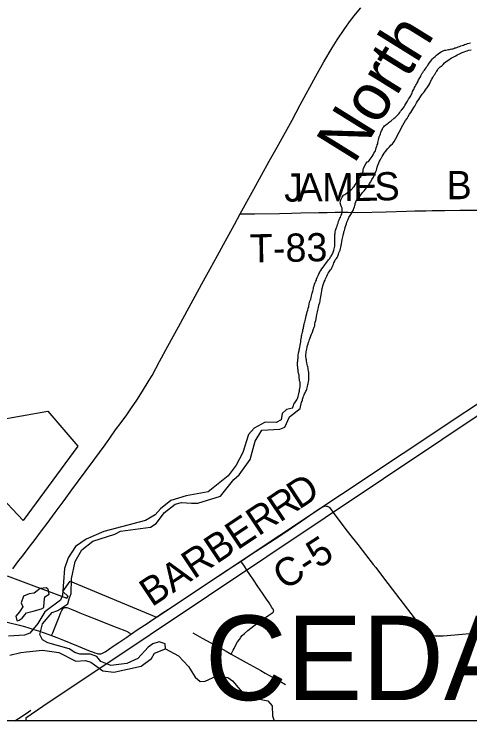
# Model space of a CAD drawing. Extents: x -19.5 to 44.1, y 0 to 22.
# Drawn here: x 4.397 to 5.315, y 17.897 to 19.322 of the extents above; entities that cross this region are included whole.
import ezdxf

# ---------------------------------------------------------------- set-up
doc = ezdxf.new("R2010")
doc.units = 0
for name, color, linetype in [('GM_X_City_Street', 7, 'Continuous'), ('GM_X_Corporation', 7, 'Continuous'), ('GM_X_County_Road', 7, 'Continuous'), ('GM_X_County_Road_Text', 7, 'Continuous'), ('GM_X_Minor_Lake', 7, 'Continuous'), ('GM_X_Minor_River', 7, 'Continuous'), ('GM_X_Minor_River_Text', 7, 'Continuous'), ('GM_X_Township_Road', 7, 'Continuous'), ('GM_X_Township_Road_Text', 7, 'Continuous'), ('GM_X_Township_Subdivision', 7, 'Continuous'), ('GM_X_Township_Text', 7, 'Continuous'), ('GM_X_US_Route', 7, 'Continuous'), ('SH_Data', 7, 'Continuous')]:
    doc.layers.add(name, color=color, linetype=linetype)

msp = doc.modelspace()

# ---------------------------------------------------------------- linework, layer by layer
at = {"layer": 'GM_X_City_Street'}
for points in [[(5.0264, 18.3303), (5.0279, 18.3302), (5.0292, 18.3297), (5.0305, 18.329), (5.0317, 18.328), (5.0344, 18.3248)], [(5.0344, 18.3248), (5.035, 18.3241), (5.0397, 18.3174)], [(4.8612, 18.2088), (4.8563, 18.2164), (4.8544, 18.2194)], [(4.8662, 18.2012), (4.8612, 18.2088)], [(4.4728, 18.0694), (4.474, 18.0721), (4.4751, 18.0745), (4.48, 18.0866), (4.4867, 18.1034), (4.4918, 18.1155), (4.4938, 18.1201), (4.4954, 18.1231), (4.496, 18.1239), (4.4967, 18.1245), (4.4979, 18.1253), (4.4994, 18.1258)], [(4.4994, 18.1258), (4.5011, 18.126), (4.5036, 18.1258), (4.5053, 18.1253), (4.5087, 18.1239), (4.516, 18.1211), (4.5237, 18.1179), (4.5298, 18.1154), (4.5433, 18.1099), (4.5638, 18.1016), (4.5988, 18.0878), (4.6063, 18.085), (4.6207, 18.0792), (4.6236, 18.078), (4.6263, 18.0766), (4.6281, 18.0757), (4.6296, 18.0745), (4.6308, 18.0731), (4.632, 18.0716)], [(4.3518, 18.1035), (4.363, 18.1009), (4.4081, 18.0901), (4.4183, 18.0872), (4.4273, 18.0848), (4.4374, 18.0817), (4.4464, 18.0786), (4.4582, 18.0746), (4.4726, 18.0694), (4.4728, 18.0694)], [(4.632, 18.0716), (4.647, 18.0819), (4.6651, 18.0939), (4.6749, 18.1005), (4.684, 18.1063)], [(4.4728, 18.0694), (4.4834, 18.0652), (4.4971, 18.0598), (4.5266, 18.048), (4.5508, 18.0381), (4.5552, 18.0365), (4.5601, 18.0347), (4.5647, 18.0331), (4.5667, 18.0327), (4.5682, 18.0324), (4.57, 18.0324)], [(4.57, 18.0324), (4.572, 18.0327), (4.574, 18.0332), (4.5756, 18.0338), (4.5769, 18.0344), (4.5807, 18.0365), (4.5874, 18.0409), (4.5991, 18.0492), (4.6084, 18.0555), (4.6245, 18.0662), (4.632, 18.0716)], [(4.3988, 17.8973), (4.4134, 17.9069), (4.4265, 17.9158), (4.431, 17.919)]]:
    msp.add_lwpolyline(points, dxfattribs=at)
at = {"layer": 'GM_X_Corporation'}
for points in [[(5.9639, 18.9356), (4.6712, 18.0706), (4.4553, 17.9261), (4.4208, 17.903), (4.4213, 17.8973), (3.9099, 17.8973), (3.9093, 17.9023), (3.9787, 17.9347), (4.0003, 17.9368), (4.0039, 17.977), (3.9735, 17.9646), (3.9645, 17.9824), (3.9246, 17.9471), (3.9155, 17.939), (3.9091, 17.934), (3.8943, 17.9218), (3.8888, 17.9158), (3.8811, 17.908), (3.8706, 17.8973), (3.5544, 17.8973), (3.5192, 17.9083)], [(4.3834, 18.1894), (4.5034, 18.1448), (4.5061, 18.148), (4.4957, 18.1583), (4.5103, 18.1788), (4.684, 18.1063), (5.9282, 18.9339)], [(4.3589, 18.5029), (4.4654, 18.5216), (4.5258, 18.451), (4.4159, 18.3009), (4.3621, 18.3579)]]:
    msp.add_lwpolyline(points, dxfattribs=at)
at = {"layer": 'GM_X_County_Road'}
for points in [[(4.8544, 18.2194), (4.8743, 18.2324), (4.9304, 18.2691), (4.9531, 18.2842), (4.9767, 18.3004), (5.01, 18.3233), (5.0141, 18.3261), (5.0193, 18.329), (5.0212, 18.3298), (5.0228, 18.3302), (5.0248, 18.3304), (5.0264, 18.3303)], [(5.0397, 18.3174), (5.0638, 18.2854), (5.0729, 18.2736), (5.0894, 18.2527), (5.1208, 18.2125), (5.1258, 18.2062), (5.1434, 18.1829), (5.1965, 18.114), (5.216, 18.0882), (5.2208, 18.0826), (5.2239, 18.0796), (5.2264, 18.0773), (5.2289, 18.0754), (5.2315, 18.0737), (5.2342, 18.0723), (5.2371, 18.0711), (5.2398, 18.0701), (5.2429, 18.0694), (5.2463, 18.0689), (5.2498, 18.0686), (5.2551, 18.0685), (5.2612, 18.0687), (5.2699, 18.0693), (5.3454, 18.076)], [(4.684, 18.1063), (4.6956, 18.1142), (4.7086, 18.1227), (4.7568, 18.1545), (4.7883, 18.1755), (4.8208, 18.1974), (4.8544, 18.2194)]]:
    msp.add_lwpolyline(points, dxfattribs=at)
at = {"layer": 'GM_X_Minor_Lake'}
for points in [[(4.436, 18.1182), (4.4524, 18.1233), (4.4574, 18.1255), (4.4576, 18.1373), (4.4596, 18.1475), (4.4677, 18.153), (4.4663, 18.1625), (4.4618, 18.1653), (4.4496, 18.164), (4.4377, 18.155), (4.4274, 18.1533), (4.416, 18.1485), (4.4116, 18.135), (4.4153, 18.1273), (4.4083, 18.1172), (4.4009, 18.1082), (4.4031, 18.0998)], [(4.4031, 18.0998), (4.4044, 18.099), (4.4076, 18.1005), (4.4137, 18.1042), (4.4193, 18.1113), (4.4224, 18.1151), (4.436, 18.1182)]]:
    msp.add_lwpolyline(points, dxfattribs=at)
at = {"layer": 'GM_X_Minor_River'}
for points in [[(5.1375, 19.0866), (5.1387, 19.0885), (5.1403, 19.0922), (5.1422, 19.0945), (5.1433, 19.0964), (5.1457, 19.0982), (5.1487, 19.1005), (5.151, 19.102), (5.1526, 19.1038), (5.1548, 19.1053), (5.1568, 19.1068), (5.1629, 19.1117), (5.1648, 19.1132), (5.1675, 19.1158), (5.1706, 19.1192), (5.1721, 19.121), (5.1741, 19.1237), (5.1756, 19.1259), (5.1775, 19.1282), (5.1814, 19.1327), (5.1829, 19.1349), (5.1841, 19.1376), (5.1884, 19.144), (5.1899, 19.1466), (5.1919, 19.15), (5.1938, 19.153), (5.1953, 19.1553), (5.1961, 19.1572), (5.1969, 19.1591), (5.1981, 19.1613), (5.1989, 19.1632), (5.2, 19.1659), (5.2016, 19.1689), (5.2028, 19.1711), (5.2035, 19.1738), (5.2051, 19.176), (5.2063, 19.1783), (5.2078, 19.1802), (5.2082, 19.1821), (5.2105, 19.1855), (5.2109, 19.1874), (5.2121, 19.1892), (5.2133, 19.1915), (5.2144, 19.1934), (5.2156, 19.1956), (5.2167, 19.1975), (5.2179, 19.1998), (5.2191, 19.2024), (5.2206, 19.2043), (5.2222, 19.2066), (5.2237, 19.2088), (5.2253, 19.2111), (5.2272, 19.2137), (5.2288, 19.2164), (5.2303, 19.2182), (5.2315, 19.2201), (5.2357, 19.2261), (5.238, 19.2291), (5.2403, 19.2318), (5.2423, 19.2333), (5.2457, 19.2366), (5.248, 19.2389), (5.2515, 19.2415), (5.2538, 19.2434), (5.2572, 19.2456), (5.2603, 19.2471), (5.2626, 19.2482), (5.2648, 19.2489), (5.2671, 19.2492), (5.2694, 19.25), (5.2725, 19.2503), (5.2744, 19.2507), (5.2763, 19.251), (5.2789, 19.2517), (5.2808, 19.2517), (5.2827, 19.2524), (5.285, 19.2535), (5.2869, 19.2539), (5.2892, 19.2546), (5.2915, 19.2557), (5.2942, 19.2565), (5.2968, 19.2576), (5.2995, 19.2583), (5.3022, 19.2594), (5.3045, 19.2605), (5.3079, 19.2612), (5.3106, 19.2623), (5.3136, 19.2634), (5.3167, 19.2641)], [(5.2387, 19.1904), (5.241, 19.1941), (5.2429, 19.1979), (5.2445, 19.2002), (5.246, 19.2024), (5.2476, 19.2051), (5.2488, 19.207), (5.2499, 19.2088), (5.2511, 19.2107), (5.2534, 19.2137), (5.2553, 19.2156), (5.2572, 19.2171), (5.2592, 19.2182), (5.2615, 19.2204), (5.2642, 19.2234), (5.2672, 19.2257), (5.2733, 19.2302), (5.2756, 19.2313), (5.2783, 19.2335), (5.2818, 19.235), (5.2841, 19.2365), (5.2867, 19.2379), (5.2898, 19.2394), (5.2928, 19.2409), (5.2959, 19.2424), (5.2997, 19.2442), (5.3035, 19.2457), (5.307, 19.2468), (5.31, 19.2479), (5.3134, 19.249), (5.3176, 19.25)], [(5.0529, 18.8435), (5.054, 18.8461), (5.0548, 18.8492), (5.0556, 18.8518), (5.0564, 18.8552), (5.0569, 18.8586), (5.0573, 18.8628), (5.0581, 18.8673), (5.0589, 18.87), (5.0593, 18.8726), (5.0601, 18.8757), (5.0609, 18.8787), (5.0613, 18.881), (5.0617, 18.8829), (5.0625, 18.8855), (5.0633, 18.8885), (5.0641, 18.892), (5.0653, 18.8954), (5.0665, 18.8991), (5.0677, 18.9025), (5.0692, 18.9067), (5.0712, 18.9116), (5.0766, 18.9199), (5.0778, 18.9222), (5.0789, 18.924), (5.0809, 18.9274), (5.0817, 18.9301), (5.0828, 18.9331), (5.0836, 18.9357), (5.084, 18.938), (5.0844, 18.9399), (5.0856, 18.9437), (5.0864, 18.9456), (5.088, 18.9478), (5.0891, 18.9497), (5.0907, 18.9527), (5.0937, 18.955), (5.0961, 18.9584), (5.0991, 18.9621), (5.1022, 18.9655), (5.1049, 18.9689), (5.1072, 18.9715), (5.1092, 18.9741), (5.1115, 18.9771), (5.1134, 18.9802), (5.1157, 18.9839), (5.1181, 18.9881), (5.1212, 18.9933), (5.1231, 18.9975), (5.1247, 19.0009), (5.1259, 19.0043), (5.127, 19.0073), (5.1278, 19.01), (5.1286, 19.0134), (5.1302, 19.0175), (5.1318, 19.0217), (5.1333, 19.0251), (5.1349, 19.0273), (5.1361, 19.0304), (5.1376, 19.0322), (5.1388, 19.0345), (5.1407, 19.0379), (5.143, 19.0417), (5.1461, 19.0458), (5.1496, 19.0503), (5.1531, 19.0541), (5.1562, 19.0574), (5.1592, 19.0604), (5.1615, 19.0631), (5.1631, 19.0653), (5.1658, 19.0698), (5.1732, 19.0838), (5.1755, 19.0883), (5.1779, 19.0932), (5.1806, 19.0977), (5.1829, 19.1023), (5.1856, 19.1072), (5.1887, 19.1113), (5.191, 19.1154), (5.1938, 19.12), (5.1965, 19.1233), (5.1984, 19.1267), (5.2003, 19.1301), (5.2023, 19.1335), (5.2042, 19.1365), (5.2058, 19.1392), (5.2077, 19.1426), (5.21, 19.1463), (5.2123, 19.1493), (5.2143, 19.1527), (5.2166, 19.1561), (5.2193, 19.1603), (5.2216, 19.1629), (5.2236, 19.1659), (5.2259, 19.1689), (5.2282, 19.1715), (5.2301, 19.1745), (5.2325, 19.1783), (5.2344, 19.1821), (5.2363, 19.1858), (5.2387, 19.1904)], [(5.0252, 18.8192), (5.0264, 18.8211), (5.0291, 18.8244), (5.0306, 18.8267), (5.0333, 18.8289), (5.0349, 18.8323), (5.036, 18.8342), (5.0372, 18.8361), (5.0399, 18.8418), (5.0411, 18.8459), (5.0419, 18.849), (5.0427, 18.8516), (5.0431, 18.8543), (5.0435, 18.8573), (5.0436, 18.8607), (5.0433, 18.8641), (5.0433, 18.8668), (5.0433, 18.8695), (5.0434, 18.8729), (5.0434, 18.8752), (5.0434, 18.8774), (5.0438, 18.8797), (5.0442, 18.8827), (5.045, 18.8854), (5.0462, 18.8896), (5.047, 18.8918), (5.0478, 18.8945), (5.0486, 18.8975), (5.0498, 18.9005), (5.051, 18.9043), (5.0521, 18.9069), (5.0525, 18.9088), (5.0533, 18.9107), (5.0545, 18.9126), (5.0553, 18.9149), (5.0564, 18.9168), (5.0572, 18.9187), (5.0584, 18.9224), (5.0584, 18.9255), (5.0581, 18.9274), (5.0578, 18.9308), (5.0566, 18.9331), (5.0556, 18.9369), (5.0541, 18.9411), (5.0545, 18.9438), (5.0553, 18.9468), (5.0561, 18.9491), (5.058, 18.9525), (5.0592, 18.9547), (5.0611, 18.9566), (5.0634, 18.9585), (5.0653, 18.9596), (5.068, 18.9614), (5.0711, 18.9641), (5.073, 18.9655), (5.0749, 18.967), (5.0768, 18.9685), (5.0788, 18.9704), (5.0803, 18.9727), (5.0822, 18.9741), (5.0842, 18.9775), (5.0861, 18.9802), (5.0876, 18.9824), (5.0892, 18.9858), (5.0919, 18.9888), (5.0938, 18.9915), (5.095, 18.9933), (5.0961, 18.9952), (5.0969, 18.9975), (5.0985, 19.0001), (5.0997, 19.0032), (5.1001, 19.005), (5.1005, 19.0077), (5.1013, 19.0104), (5.1021, 19.0138), (5.1056, 19.0202), (5.1087, 19.0239), (5.1109, 19.025), (5.1133, 19.0277), (5.1144, 19.0295), (5.1163, 19.0322), (5.1187, 19.0348), (5.1206, 19.0378), (5.1222, 19.0416), (5.1241, 19.0442), (5.1249, 19.0461), (5.1261, 19.0491), (5.1269, 19.0525), (5.128, 19.0556), (5.1288, 19.0582), (5.1296, 19.0605), (5.13, 19.0628), (5.1308, 19.0654), (5.1316, 19.0684), (5.132, 19.0711), (5.1328, 19.0741), (5.134, 19.0768), (5.1348, 19.0786), (5.1352, 19.0805), (5.1363, 19.0828), (5.1375, 19.0866)], [(4.9735, 18.5272), (4.9762, 18.5399), (4.9773, 18.5417), (4.9781, 18.5436), (4.9785, 18.5455), (4.9797, 18.5489), (4.9805, 18.5519), (4.9817, 18.5546), (4.9825, 18.5565), (4.9836, 18.5584), (4.9852, 18.5618), (4.986, 18.5636), (4.9871, 18.5659), (4.9879, 18.5686), (4.9883, 18.5712), (4.9891, 18.575), (4.9899, 18.5776), (4.9904, 18.5814), (4.9908, 18.5841), (4.9908, 18.5871), (4.9912, 18.5898), (4.9913, 18.5925), (4.9913, 18.5947), (4.9909, 18.5974), (4.991, 18.5993), (4.9906, 18.6031), (4.9899, 18.6054), (4.9896, 18.6084), (4.9888, 18.6107), (4.9885, 18.613), (4.9877, 18.6153), (4.987, 18.6195), (4.9863, 18.6225), (4.986, 18.6248), (4.9856, 18.6267), (4.9856, 18.6286), (4.9849, 18.6313), (4.9849, 18.6332), (4.985, 18.6355), (4.9854, 18.6381), (4.9858, 18.6412), (4.9862, 18.6438), (4.987, 18.6465), (4.9878, 18.6503), (4.9886, 18.654), (4.9898, 18.6574), (4.9906, 18.6609), (4.9918, 18.6631), (4.9922, 18.6662), (4.9934, 18.6696), (4.9949, 18.673), (4.9961, 18.6767), (4.9981, 18.6809), (5, 18.6854), (5.0016, 18.6907), (5.0028, 18.6934), (5.0032, 18.6971), (5.004, 18.7009), (5.0048, 18.704), (5.0056, 18.7078), (5.0064, 18.7123), (5.0072, 18.7165), (5.0081, 18.7214), (5.0092, 18.7252), (5.0101, 18.7301), (5.0113, 18.7354), (5.0129, 18.7407), (5.0136, 18.7434), (5.014, 18.7452), (5.0145, 18.7483), (5.0153, 18.7525), (5.0157, 18.7562), (5.0165, 18.7597), (5.0169, 18.7638), (5.0178, 18.7684), (5.0185, 18.771), (5.0194, 18.7744), (5.0221, 18.7824), (5.0237, 18.7854), (5.0245, 18.788), (5.026, 18.7907), (5.0272, 18.7937), (5.0287, 18.7967), (5.0299, 18.7997), (5.0318, 18.8024), (5.0349, 18.8061), (5.0365, 18.8084), (5.0376, 18.8106), (5.0384, 18.8129), (5.0396, 18.8152), (5.0408, 18.8178), (5.0416, 18.8205), (5.0427, 18.8227), (5.0443, 18.8265), (5.0466, 18.8291), (5.0482, 18.8314), (5.0497, 18.834), (5.0501, 18.8359), (5.0509, 18.8378), (5.0517, 18.8405), (5.0529, 18.8435)], [(4.9581, 18.5275), (4.9601, 18.5329), (4.9609, 18.5359), (4.9629, 18.5385), (4.9671, 18.5445), (4.9679, 18.5468), (4.9691, 18.5491), (4.9695, 18.551), (4.9699, 18.5536), (4.9707, 18.5566), (4.9715, 18.5601), (4.9719, 18.562), (4.9723, 18.5646), (4.9731, 18.5676), (4.9735, 18.5707), (4.9736, 18.5737), (4.9732, 18.5756), (4.9732, 18.5779), (4.9733, 18.5802), (4.9725, 18.5825), (4.9722, 18.5855), (4.9718, 18.5885), (4.9715, 18.5912), (4.9712, 18.5939), (4.9708, 18.5958), (4.9704, 18.5977), (4.9697, 18.6019), (4.9694, 18.6049), (4.969, 18.6068), (4.9687, 18.6099), (4.968, 18.6137), (4.968, 18.6171), (4.9684, 18.6201), (4.9685, 18.6224), (4.9689, 18.6243), (4.9689, 18.6262), (4.9693, 18.6285), (4.9694, 18.6319), (4.9698, 18.6349), (4.9702, 18.6376), (4.971, 18.641), (4.9714, 18.6429), (4.9718, 18.6452), (4.9722, 18.6471), (4.9726, 18.6505), (4.9734, 18.6546), (4.9739, 18.6581), (4.9746, 18.6607), (4.9751, 18.6641), (4.9755, 18.6675), (4.9763, 18.6706), (4.9763, 18.6732), (4.9771, 18.6755), (4.9775, 18.6781), (4.9779, 18.6804), (4.9787, 18.6827), (4.9791, 18.6857), (4.9799, 18.6887), (4.9803, 18.6906), (4.9807, 18.6925), (4.9811, 18.6948), (4.9819, 18.6971), (4.9823, 18.6993), (4.9828, 18.7016), (4.9835, 18.7039), (4.984, 18.7069), (4.9848, 18.71), (4.9859, 18.7137), (4.9871, 18.7183), (4.9879, 18.7217), (4.9887, 18.7251), (4.9896, 18.7293), (4.9907, 18.7327), (4.9919, 18.738), (4.9931, 18.7433), (4.9947, 18.747), (4.9955, 18.7497), (4.9963, 18.7539), (4.9975, 18.7595), (4.9987, 18.7633), (4.9995, 18.766), (5.0003, 18.769), (5.0007, 18.7713), (5.0015, 18.7739), (5.0027, 18.7773), (5.0039, 18.7807), (5.005, 18.7838), (5.0062, 18.7856), (5.0066, 18.7875), (5.0078, 18.7906), (5.009, 18.7936), (5.0101, 18.7962), (5.0113, 18.7985), (5.0125, 18.8004), (5.0132, 18.8023), (5.0152, 18.8049), (5.0171, 18.8083), (5.0198, 18.8117), (5.0221, 18.8143), (5.0229, 18.8162), (5.0252, 18.8192)], [(4.9581, 18.5275), (4.9457, 18.5248), (4.9374, 18.5165), (4.9353, 18.504), (4.925, 18.4988), (4.9029, 18.4992), (4.8807, 18.4874), (4.8695, 18.4743), (4.8579, 18.438), (4.8446, 18.4128), (4.8283, 18.3914), (4.7879, 18.3586), (4.7442, 18.3506), (4.7129, 18.3412), (4.6925, 18.3245), (4.6817, 18.3125), (4.6618, 18.301), (4.5779, 18.2792), (4.5427, 18.2635), (4.5212, 18.249), (4.5061, 18.2261), (4.4989, 18.2045), (4.4946, 18.1507), (4.4906, 18.1405), (4.4591, 18.1171), (4.4455, 18.0938), (4.4288, 18.0743), (4.4181, 18.0703), (4.3862, 18.0682)], [(4.389, 18.0298), (4.4107, 18.0351), (4.4222, 18.0368), (4.4545, 18.0397), (4.4878, 18.035), (4.5217, 18.0174), (4.5414, 18.019), (4.552, 18.0158), (4.5764, 17.9979), (4.5984, 17.9953), (4.6536, 18.0077), (4.6744, 18.0233), (4.6802, 18.0335), (4.702, 18.0422), (4.7014, 18.0525), (4.6893, 18.0568), (4.6771, 18.0529), (4.6675, 18.0462), (4.6463, 18.023), (4.6241, 18.0127), (4.5925, 18.0087), (4.5721, 18.017), (4.564, 18.027), (4.5515, 18.0317), (4.5299, 18.0321), (4.5197, 18.0353), (4.5084, 18.0427), (4.465, 18.0547), (4.4544, 18.0606), (4.4489, 18.0713), (4.4549, 18.0929), (4.4743, 18.1157), (4.4857, 18.1197), (4.5053, 18.1334), (4.5085, 18.1433), (4.5121, 18.1538), (4.513, 18.1834), (4.5204, 18.2186), (4.534, 18.2423), (4.556, 18.2598), (4.6004, 18.2735), (4.6114, 18.2797), (4.6718, 18.288), (4.6833, 18.2954), (4.7004, 18.3175), (4.7219, 18.3339), (4.7345, 18.3375), (4.7546, 18.3364), (4.7671, 18.3358), (4.8132, 18.3502), (4.84, 18.3836), (4.8507, 18.3929), (4.8729, 18.4241), (4.8826, 18.4608), (4.8966, 18.4833), (4.9323, 18.4854), (4.9426, 18.489), (4.9517, 18.5102), (4.9735, 18.5272)], [(4.702, 18.0422), (4.7283, 18.0281), (4.7485, 18.0069), (4.7618, 17.9855), (4.7723, 17.9766), (4.7822, 17.9775), (4.8055, 17.9878), (4.8275, 17.9848), (4.8372, 17.9782), (4.864, 17.9462), (4.9083, 17.9379), (4.9173, 17.9275), (4.9177, 17.9074), (4.9211, 17.8973)]]:
    msp.add_lwpolyline(points, dxfattribs=at)
at = {"layer": 'GM_X_Township_Road'}
msp.add_lwpolyline([(4.8527, 18.919), (4.8825, 18.9192), (4.9316, 18.92), (4.9558, 18.9205), (4.975, 18.9209), (5.011, 18.9216), (5.0278, 18.9219), (5.0439, 18.9224), (5.0594, 18.9227), (5.07, 18.9226), (5.0898, 18.9222), (5.1464, 18.9235), (5.1878, 18.9247), (5.2044, 18.9252), (5.2267, 18.9254), (5.2391, 18.9256), (5.2652, 18.9261), (5.295, 18.9264), (5.308, 18.9266), (5.3335, 18.9268)], dxfattribs=at)
at = {"layer": 'GM_X_Township_Subdivision'}
for points in [[(4.9204, 18.1185), (4.9201, 18.1199), (4.9196, 18.1213), (4.919, 18.1224), (4.9185, 18.1234), (4.9167, 18.1261), (4.911, 18.1349), (4.9057, 18.1426), (4.903, 18.1468), (4.8974, 18.155), (4.8883, 18.1684), (4.8797, 18.1813), (4.872, 18.1926), (4.8662, 18.2012)], [(4.8344, 18.032), (4.8373, 18.0374), (4.8385, 18.0396), (4.8405, 18.0433), (4.8429, 18.0477), (4.8476, 18.0564), (4.851, 18.0616), (4.8542, 18.0661), (4.857, 18.0694), (4.8611, 18.0733), (4.8683, 18.0792), (4.8805, 18.0886), (4.895, 18.0994), (4.9106, 18.1105), (4.9184, 18.1156), (4.9192, 18.1164), (4.9198, 18.117), (4.9201, 18.1176), (4.9204, 18.1185)], [(4.7574, 18.0746), (4.7759, 18.0643), (4.7938, 18.0545), (4.7998, 18.0512), (4.8102, 18.0455), (4.8183, 18.0409), (4.8243, 18.0376), (4.8344, 18.032)], [(4.8344, 18.032), (4.8468, 18.0251), (4.8647, 18.0151), (4.8941, 17.999), (4.9033, 17.9938), (4.9237, 17.982), (4.9285, 17.9792), (4.9323, 17.9771), (4.9437, 17.9706)]]:
    msp.add_lwpolyline(points, dxfattribs=at)
at = {"layer": 'GM_X_US_Route'}
msp.add_lwpolyline([(4.3948, 18.204), (4.4052, 18.2179), (4.4162, 18.2322), (4.4278, 18.2476), (4.4396, 18.2628), (4.4525, 18.2803), (4.4637, 18.2952), (4.48, 18.3172), (4.498, 18.3418), (4.5136, 18.3627), (4.5249, 18.3783), (4.5404, 18.3993), (4.5577, 18.4228), (4.5808, 18.4537), (4.5905, 18.4673), (4.6019, 18.4837), (4.613, 18.4987), (4.6242, 18.5143), (4.634, 18.5279), (4.6444, 18.5434), (4.6561, 18.5617), (4.6696, 18.584), (4.6752, 18.5937), (4.6904, 18.6215), (4.7073, 18.6526), (4.7284, 18.6913), (4.75, 18.7313), (4.7619, 18.7531), (4.7757, 18.7781), (4.7925, 18.8086), (4.8071, 18.8353), (4.8232, 18.8648), (4.8299, 18.8767), (4.8412, 18.8974), (4.8527, 18.919), (4.88, 18.9689), (4.9112, 19.0255), (4.9269, 19.0537), (4.9571, 19.108), (4.9736, 19.1387), (5.005, 19.1965), (5.0214, 19.2258), (5.0379, 19.2535), (5.048, 19.2699), (5.0637, 19.293), (5.0748, 19.3087), (5.0847, 19.3213), (5.0955, 19.3341)], dxfattribs=at)
at = {"layer": 'SH_Data'}
msp.add_line((9.4, 17.8973), (2.6, 17.8973), dxfattribs=at)

# ---------------------------------------------------------------- texts
at = {"layer": 'GM_X_County_Road_Text'}
for s, height, rotation, p in [('D', 0.0568, 33.2384, (4.9711, 18.3223)), ('R', 0.0568, 33.9445, (4.9325, 18.2963)), ('BARBER', 0.05682, 33.6425, (4.6748, 18.1259)), ('C-5', 0.05682, 32.822, (4.9424, 18.1594))]:
    msp.add_text(s, height=height, rotation=rotation, dxfattribs=at).set_placement(p)
at = {"layer": 'GM_X_Minor_River_Text'}
msp.add_text('North', height=0.09468, rotation=58.1472, dxfattribs=at).set_placement((5.0819, 19.0174))
at = {"layer": 'GM_X_Township_Road_Text'}
for s, height, rotation, p in [('J', 0.0568, 0.806, (4.9415, 18.9436)), ('A', 0.0568, 0.8092, (4.9681, 18.944)), ('M', 0.0568, 0.062, (5.0179, 18.9447)), ('E', 0.0568, 1.0417, (5.0807, 18.9448)), ('S', 0.0568, 1.8279, (5.124, 18.9456)), ('B', 0.0568, 0.2771, (5.2685, 18.9486)), ('T-83', 0.05682, 1.0639, (4.8726, 18.821))]:
    msp.add_text(s, height=height, rotation=rotation, dxfattribs=at).set_placement(p)
at = {"layer": 'GM_X_Township_Text'}
msp.add_text('CEDARVILLE', height=0.17045, rotation=0, dxfattribs=at).set_placement((4.7818, 17.9391))

doc.saveas('drawing.dxf')
